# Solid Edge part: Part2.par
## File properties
Author: Deepak Maini
Template: Normal.par
Last saved by: Robert a Rhodes jr
Revision: 11
Application: Solid Edge
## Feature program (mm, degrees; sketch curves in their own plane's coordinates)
sketch for "unnamed Protrusion 1" plane through (0, 0, 0) normal (0, -1, 0) x-axis (1, 0, 0)
  line (-41.5864, -1.056) -> (-41.5864, 10.944)
  line (-41.5864, 10.944) -> (58.4136, 10.944)
  arc centre (58.4136, 25.944) radius 15 from (58.4136, 10.944) to (70.6346, 34.6415) ccw
  line (70.6346, 34.6415) -> (76.9484, 45.5772)
  arc centre (58.4136, 25.944) radius 27 from (58.4136, -1.056) to (76.9484, 45.5772) ccw
  line (58.4136, -1.056) -> (-41.5864, -1.056)
extrude "unnamed Protrusion 1" add finite 50 along +normal
sketch for "unnamed Protrusion 2" #1 plane through (-44.5864, -25, 4.1402) normal (-0.866025, 0, -0.5) x-axis (0, -1, 0)
  line (-15, 28) -> (-15, 73)
  arc centre (-10, 73) radius 5 from (-5, 73) to (-15, 73) ccw
  line (-5, 73) -> (-5, 36)
  line (-5, 36) -> (5, 36)
  line (5, 36) -> (5, 61)
  arc centre (10, 61) radius 5 from (5, 61) to (15, 61) cw
  line (15, 61) -> (15, 28)
  arc centre (0, 28) radius 15 from (-15, 28) to (15, 28) ccw
sketch for "unnamed Protrusion 2" #2 plane through (-44.5864, -25, 4.1402) normal (-0.866025, 0, -0.5) x-axis (0, -1, 0)
  arc centre (-19, 84) radius 6 from (-25, 84) to (-16.2055, 89.3095) cw
  line (-16.2055, 89.3095) -> (21.7945, 69.3095)
  arc centre (19, 64) radius 6 from (21.7945, 69.3095) to (25, 64) cw
  line (25, 64) -> (25, -6)
  line (25, -6) -> (-25, -6)
  line (-25, 84) -> (-25, -6)
extrude "unnamed Protrusion 2" add finite 12 along -normal
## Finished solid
Body 1: solid body, 20 faces, 54 edges, 36 vertices.
  Faces by surface: plane 13, cylinder 7
  Edges by curve: line 40, circle 14
Bounding box of the edges (mm): 175.000 x 50.000 x 89.138, from (-89.5864, -50, -1.056) to (85.4136, 0, 88.0824).
Cylindrical faces by radius (mm): R5 x2, R6 x2, R15 x2, R27 x1
Planar faces by outward normal: +y 3, +z 1, -y 3, -z 1, oblique 5
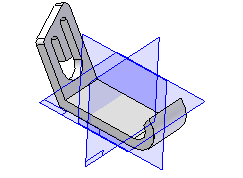
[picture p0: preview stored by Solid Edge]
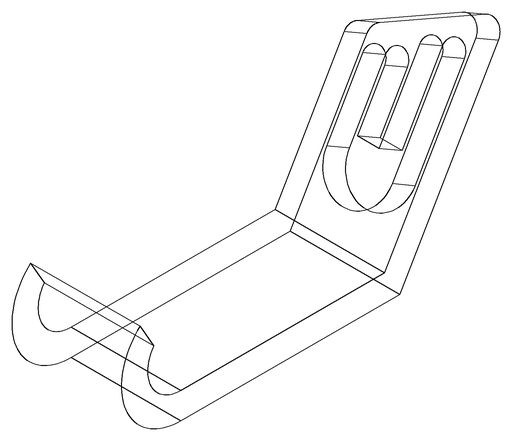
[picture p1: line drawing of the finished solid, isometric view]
